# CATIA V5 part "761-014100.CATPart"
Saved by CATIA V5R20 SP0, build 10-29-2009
Part number: 761-014100
Source: Unknown
Property "ARTICLENO": "761-014100"
Property "BOMINFO": "761-014100"
Property "CODE": "761-014100"
Property "H": "14.000"
Property "L1": "100.000"
Property "L2": "80.000"
Property "LINA": "761-014100"
Property "NB": "761-014100"
Property "NBSYN": "$CODE."
Property "NN": "761"
Property "NT": "VW/AUDI Keys"
Property "P": "0.000"
Property "SUPPLIER": "CF"
Bounding box of the stored display mesh (mm): x -50 to 50, y 0 to 14, z -11 to 11
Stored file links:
  C:\Users\Utente\Desktop\3D files 761\761-014100.CATPart
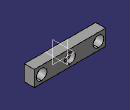
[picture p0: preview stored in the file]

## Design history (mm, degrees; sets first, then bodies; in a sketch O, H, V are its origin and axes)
Body1 "Geometry.1" (main body)
  Solid1 "761-014100.catpart": solid without history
